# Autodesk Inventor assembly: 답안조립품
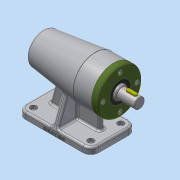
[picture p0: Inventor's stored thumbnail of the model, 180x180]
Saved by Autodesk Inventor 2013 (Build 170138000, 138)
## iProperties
Created: 2018-09
Part Number: 답안조립품
Document SubType Name: Assembly
Designer: dgall
Author: dgall
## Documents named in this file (10)
- C:\Users\dgall\Desktop\480907V1021\답안조립품.iam
- C:\Users\dgall\Desktop\480907V1021\본체.ipt
- C:\Users\dgall\Desktop\480907V1021\베어링 6004.ipt
- C:\Users\dgall\Desktop\480907V1021\베어링 51202.ipt
- C:\Users\dgall\Desktop\480907V1021\볼트 M4.ipt
- C:\Users\dgall\Desktop\480907V1021\어댑터슬리브.ipt
- C:\Users\dgall\Desktop\480907V1021\축.ipt
- C:\Users\dgall\Desktop\480907V1021\키 5 x 5 x 16.ipt
- C:\Users\dgall\Desktop\480907V1021\오일 실.ipt
- C:\Users\dgall\Desktop\480907V1021\커버.ipt
